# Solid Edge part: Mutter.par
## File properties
Sűrűség: 0,000 kg/m^3
Pontosság: 0,990
Author: ahadarics
Last saved by: psaghy
Revision: 77
Username: ahadarics
Dokumentum tartalom típus: 0
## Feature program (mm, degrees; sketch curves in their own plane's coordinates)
base feature "unnamed BaseFeature 1"
sketch for "Furat_1" plane through (12, 0, 0) normal (1, 0, 0) x-axis (0, 0, -1)
hole "Furat_1" through  StartChamferOffset = 0.62 mm; StartChamferAngle = 45 deg
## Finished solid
Body 1: solid body, 23 faces, 47 edges, 26 vertices.
  Faces by surface: cone 14, plane 8, cylinder 1
  Edges by curve: spline 24, circle 16, line 7
Bounding box of the edges (mm): 12.000 x 47.343 x 41.000, from (0, -23.6714, -20.5) to (12, 23.6714, 20.5).
Cylindrical faces by radius (mm): R12.4175 x1
Conical faces (half-angle, radius in mm at the cone's reference point): 45 deg R13.0375 x1, 60 deg R12.9588 x1, 60 deg R22.0857 x12
Planar faces by outward normal: +x 1, +z 1, -x 1, -z 1, oblique 4
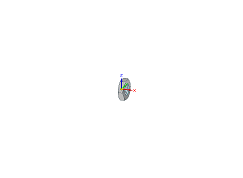
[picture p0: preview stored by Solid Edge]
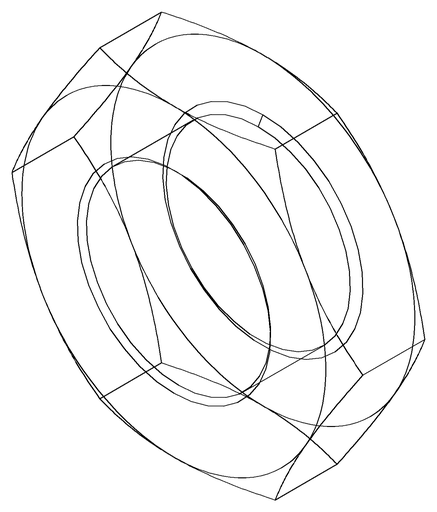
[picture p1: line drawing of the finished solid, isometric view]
